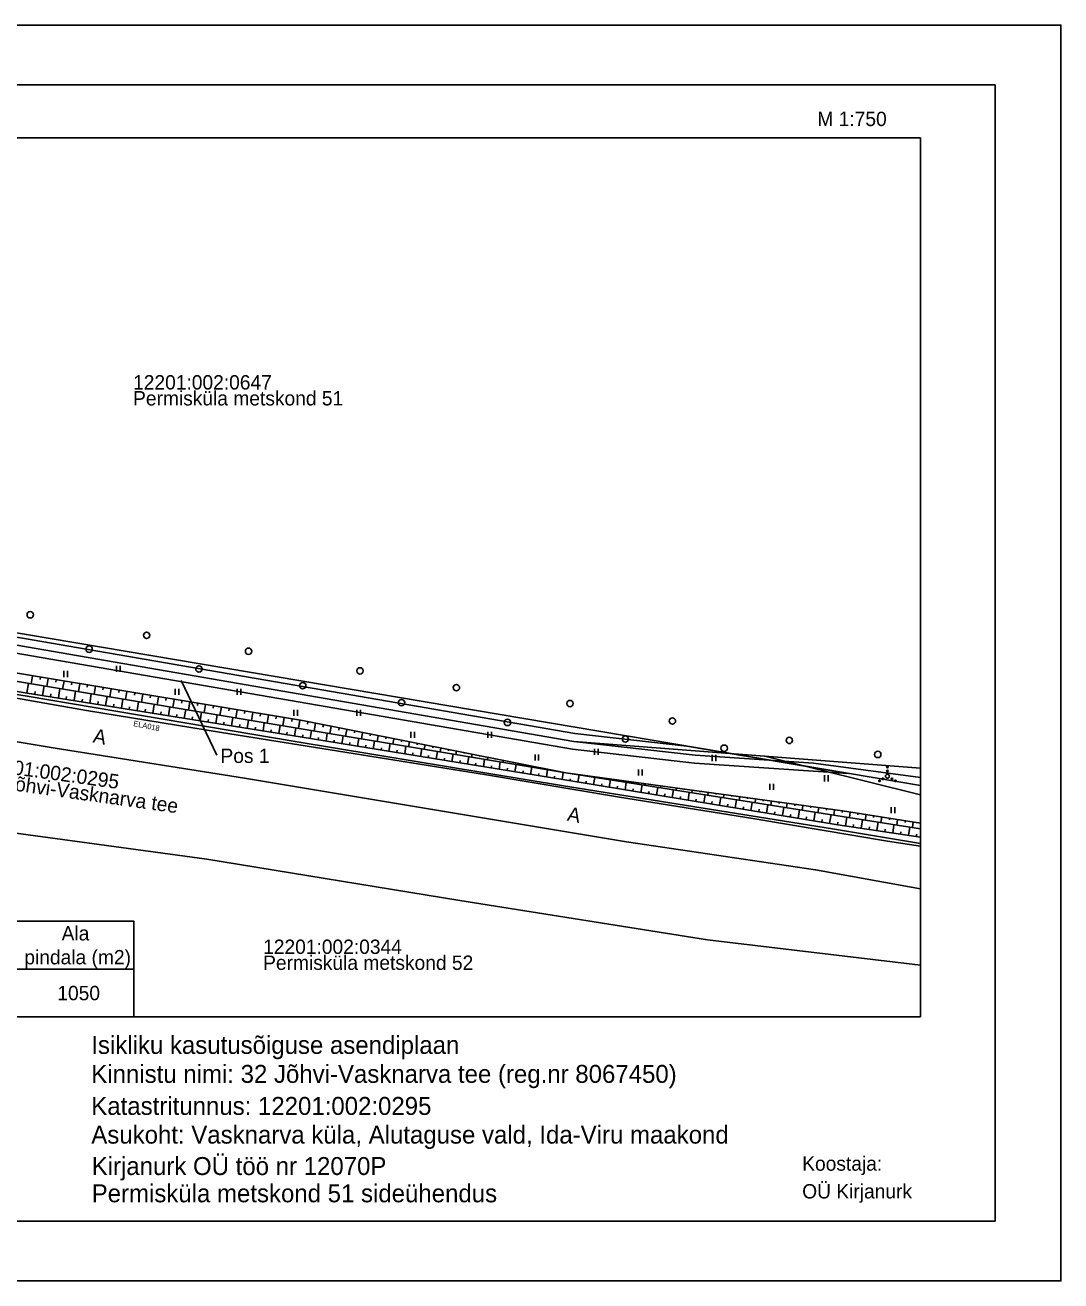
# Model space of a CAD drawing. Extents: x 712851 to 713448, y 6545714 to 6545930.
# Drawn here: x 713318.1 to 713448, y 6545714.1 to 6545871.6 of the extents above; entities that cross this region are included whole.
import ezdxf

# ---------------------------------------------------------------- set-up
doc = ezdxf.new("R2010")
doc.units = 0
for name, color, linetype in [('HALJASTUS', 7, 'Continuous'), ('KASUTUSALA', 7, 'Continuous'), ('PIIR', 7, 'Continuous'), ('PR_SIDE', 7, 'Continuous'), ('RELJEEF', 7, 'Continuous'), ('SITRASS', 7, 'Continuous'), ('TEE', 7, 'Continuous'), ('VORMISTUS_2', 7, 'Continuous')]:
    doc.layers.add(name, color=color, linetype=linetype)

msp = doc.modelspace()

# ---------------------------------------------------------------- linework, layer by layer
at = {"layer": 'HALJASTUS'}
for p, q in [((713322.93, 6545790.63), (713322.93, 6545789.87)), ((713323.39, 6545790.63), (713323.39, 6545789.87)), ((713329.55, 6545791.26), (713329.55, 6545790.5)), ((713330, 6545791.26), (713330, 6545790.5)), ((713336.91, 6545788.38), (713336.91, 6545787.62)), ((713337.36, 6545788.38), (713337.36, 6545787.62)), ((713344.69, 6545788.38), (713344.69, 6545787.62)), ((713345.14, 6545788.38), (713345.14, 6545787.62)), ((713351.78, 6545785.75), (713351.78, 6545784.99)), ((713352.24, 6545785.75), (713352.24, 6545784.99)), ((713359.68, 6545785.75), (713359.68, 6545784.99)), ((713360.14, 6545785.75), (713360.14, 6545784.99)), ((713366.48, 6545782.99), (713366.48, 6545782.23)), ((713366.93, 6545782.99), (713366.93, 6545782.23)), ((713376.11, 6545782.99), (713376.11, 6545782.23)), ((713376.57, 6545782.99), (713376.57, 6545782.23)), ((713389.52, 6545780.87), (713389.52, 6545780.11)), ((713389.98, 6545780.87), (713389.98, 6545780.11)), ((713382.04, 6545780.15), (713382.04, 6545779.39)), ((713382.49, 6545780.15), (713382.49, 6545779.39)), ((713404.24, 6545780.09), (713404.24, 6545779.33)), ((713404.7, 6545780.09), (713404.7, 6545779.33)), ((713395.03, 6545778.26), (713395.03, 6545777.5)), ((713395.48, 6545778.26), (713395.48, 6545777.5)), ((713418.34, 6545777.54), (713418.34, 6545776.78)), ((713418.8, 6545777.54), (713418.8, 6545776.78)), ((713411.49, 6545776.49), (713411.49, 6545775.73)), ((713411.94, 6545776.49), (713411.94, 6545775.73)), ((713426.69, 6545773.56), (713426.69, 6545772.8)), ((713427.15, 6545773.56), (713427.15, 6545772.8))]:
    msp.add_line(p, q, dxfattribs=at)
for points in [[(713430.38, 6545778.43), (713386.9, 6545781.8), (713288.25, 6545798.83), (713243.24, 6545806.02)], [(713430.38, 6545775.09), (713410.87, 6545779.94)]]:
    msp.add_lwpolyline(points, dxfattribs=at)
for centre, radius in [((713318.73, 6545797.68), 0.4), ((713333.33, 6545795.1), 0.4), ((713326.12, 6545793.36), 0.4), ((713346.11, 6545793.1), 0.4), ((713339.89, 6545790.88), 0.4), ((713360.09, 6545790.64), 0.4), ((713352.91, 6545788.78), 0.4), ((713372.18, 6545788.54), 0.4), ((713365.3, 6545786.66), 0.4), ((713386.43, 6545786.54), 0.4), ((713378.59, 6545784.17), 0.4), ((713399.27, 6545784.35), 0.4), ((713393.37, 6545782.1), 0.4), ((713413.93, 6545781.92), 0.4), ((713405.76, 6545780.94), 0.4), ((713425.03, 6545780.16), 0.4), ((713425.67, 6545777.1), 0.1), ((713426.24, 6545777.43), 0.25), ((713426.24, 6545778.58), 0.1), ((713426.24, 6545778.08), 0.1), ((713426.8, 6545777.1), 0.1), ((713425.24, 6545776.85), 0.1), ((713427.24, 6545776.85), 0.1)]:
    msp.add_circle(centre, radius, dxfattribs=at)
at = {"layer": 'KASUTUSALA'}
msp.add_lwpolyline([(713206.31, 6545813.05), (713233.87, 6545808.53), (713288.41, 6545799.81), (713387.04, 6545782.79), (713401.1, 6545781.2), (713421.33, 6545777.78), (713402.03, 6545779.08), (713386.76, 6545780.81), (713288.08, 6545797.84), (713233.55, 6545806.56), (713205.99, 6545811.08)], dxfattribs=at)
at = {"layer": 'PIIR'}
for points in [[(713243.24, 6545807.88), (713424.43, 6545777.26), (713430.38, 6545776.26)], [(713430.38, 6545776.26), (713424.43, 6545777.26), (713243.24, 6545807.88)], [(713243.24, 6545781.2), (713254.77, 6545779.15), (713286.79, 6545774.61), (713312.9, 6545770.82), (713340.87, 6545767.01), (713372.6, 6545761.82), (713403.67, 6545756.92), (713430.38, 6545753.73)], [(713430.38, 6545753.73), (713403.67, 6545756.92), (713372.6, 6545761.82), (713340.87, 6545767.01), (713312.9, 6545770.82), (713286.79, 6545774.61), (713254.77, 6545779.15), (713243.24, 6545781.2)]]:
    msp.add_lwpolyline(points, dxfattribs=at)
at = {"layer": 'PR_SIDE'}
msp.add_lwpolyline([(713243.24, 6545806.02), (713288.25, 6545798.83), (713386.9, 6545781.8), (713402.12, 6545780.08), (713416.97, 6545779.08), (713430.38, 6545777.27)], dxfattribs=at)
at = {"layer": 'RELJEEF'}
for p, q in [((713319.03, 6545790.03), (713318.86, 6545789.02)), ((713320.01, 6545789.86), (713319.96, 6545789.56)), ((713318.31, 6545787.87), (713318.51, 6545789.07)), ((713320.28, 6545787.55), (713320.48, 6545788.75)), ((713321, 6545789.7), (713320.83, 6545788.69)), ((713321.98, 6545789.54), (713321.93, 6545789.23)), ((713322.26, 6545787.24), (713322.45, 6545788.42)), ((713322.97, 6545789.37), (713322.8, 6545788.36)), ((713323.96, 6545789.21), (713323.91, 6545788.9)), ((713324.94, 6545789.04), (713324.78, 6545788.03)), ((713325.93, 6545788.88), (713325.88, 6545788.58)), ((713326.92, 6545788.72), (713326.75, 6545787.7)), ((713327.9, 6545788.55), (713327.85, 6545788.25)), ((713328.89, 6545788.39), (713328.72, 6545787.37)), ((713329.88, 6545788.22), (713329.83, 6545787.92)), ((713319.3, 6545787.71), (713319.35, 6545788.07)), ((713321.27, 6545787.39), (713321.33, 6545787.75)), ((713323.25, 6545787.08), (713323.3, 6545787.43)), ((713324.23, 6545786.92), (713324.42, 6545788.09)), ((713325.22, 6545786.76), (713325.28, 6545787.11)), ((713326.21, 6545786.6), (713326.39, 6545787.76)), ((713327.19, 6545786.44), (713327.25, 6545786.79)), ((713328.18, 6545786.28), (713328.37, 6545787.43)), ((713330.16, 6545785.97), (713330.34, 6545787.1)), ((713330.86, 6545788.06), (713330.69, 6545787.04)), ((713331.85, 6545787.89), (713331.8, 6545787.59)), ((713332.13, 6545785.65), (713332.31, 6545786.77)), ((713332.84, 6545787.73), (713332.67, 6545786.71)), ((713333.82, 6545787.57), (713333.77, 6545787.26)), ((713334.81, 6545787.4), (713334.64, 6545786.39)), ((713335.79, 6545787.24), (713335.74, 6545786.93)), ((713336.78, 6545787.07), (713336.61, 6545786.06)), ((713337.77, 6545786.91), (713337.72, 6545786.6)), ((713338.75, 6545786.75), (713338.58, 6545785.73)), ((713329.17, 6545786.12), (713329.22, 6545786.47)), ((713331.14, 6545785.81), (713331.2, 6545786.15)), ((713333.12, 6545785.49), (713333.17, 6545785.83)), ((713334.11, 6545785.33), (713334.28, 6545786.44)), ((713335.09, 6545785.17), (713335.15, 6545785.5)), ((713336.08, 6545785.01), (713336.26, 6545786.12)), ((713337.07, 6545784.85), (713337.12, 6545785.18)), ((713338.05, 6545784.7), (713338.23, 6545785.79)), ((713339.74, 6545786.58), (713339.69, 6545786.28)), ((713340.03, 6545784.38), (713340.2, 6545785.46)), ((713340.73, 6545786.42), (713340.56, 6545785.4)), ((713341.71, 6545786.25), (713341.66, 6545785.95)), ((713342, 6545784.06), (713342.18, 6545785.13)), ((713342.7, 6545786.09), (713342.53, 6545785.07)), ((713343.69, 6545785.92), (713343.64, 6545785.62)), ((713344.67, 6545785.76), (713344.5, 6545784.74)), ((713345.66, 6545785.6), (713345.61, 6545785.29)), ((713346.65, 6545785.43), (713346.48, 6545784.41)), ((713347.63, 6545785.27), (713347.58, 6545784.96)), ((713348.62, 6545785.1), (713348.45, 6545784.08)), ((713339.04, 6545784.54), (713339.09, 6545784.86)), ((713341.02, 6545784.22), (713341.07, 6545784.54)), ((713342.99, 6545783.9), (713343.04, 6545784.22)), ((713343.98, 6545783.74), (713344.15, 6545784.8)), ((713344.97, 6545783.58), (713345.02, 6545783.9)), ((713345.95, 6545783.43), (713346.12, 6545784.47)), ((713346.94, 6545783.27), (713346.99, 6545783.58)), ((713347.93, 6545783.11), (713348.09, 6545784.14)), ((713349.6, 6545784.94), (713349.55, 6545784.63)), ((713349.9, 6545782.79), (713350.07, 6545783.81)), ((713350.59, 6545784.78), (713350.42, 6545783.76)), ((713351.58, 6545784.61), (713351.53, 6545784.3)), ((713351.88, 6545782.47), (713352.04, 6545783.49)), ((713352.56, 6545784.45), (713352.39, 6545783.43)), ((713353.55, 6545784.26), (713353.49, 6545783.96)), ((713354.53, 6545784.07), (713354.34, 6545783.1)), ((713355.51, 6545783.87), (713355.45, 6545783.59)), ((713356.49, 6545783.68), (713356.31, 6545782.78)), ((713357.47, 6545783.48), (713357.42, 6545783.22)), ((713348.92, 6545782.95), (713348.97, 6545783.26)), ((713350.89, 6545782.63), (713350.94, 6545782.94)), ((713352.86, 6545782.31), (713352.91, 6545782.62)), ((713353.85, 6545782.15), (713354.01, 6545783.16)), ((713354.84, 6545781.99), (713354.89, 6545782.29)), ((713355.83, 6545781.83), (713355.99, 6545782.83)), ((713356.81, 6545781.67), (713356.86, 6545781.97)), ((713357.8, 6545781.51), (713357.96, 6545782.5)), ((713358.45, 6545783.29), (713358.28, 6545782.45)), ((713359.43, 6545783.1), (713359.38, 6545782.85)), ((713359.77, 6545781.19), (713359.93, 6545782.17)), ((713360.41, 6545782.9), (713360.26, 6545782.12)), ((713361.39, 6545782.71), (713361.35, 6545782.48)), ((713362.38, 6545782.51), (713362.23, 6545781.79)), ((713363.36, 6545782.32), (713363.32, 6545782.11)), ((713364.34, 6545782.12), (713364.21, 6545781.46)), ((713365.32, 6545781.93), (713365.28, 6545781.74)), ((713358.79, 6545781.35), (713358.83, 6545781.65)), ((713360.76, 6545781.03), (713360.81, 6545781.32)), ((713361.75, 6545780.87), (713361.91, 6545781.84)), ((713362.73, 6545780.71), (713362.78, 6545781)), ((713363.72, 6545780.55), (713363.88, 6545781.52)), ((713364.71, 6545780.39), (713364.76, 6545780.68)), ((713365.7, 6545780.23), (713365.85, 6545781.19)), ((713366.3, 6545781.74), (713366.18, 6545781.13)), ((713366.68, 6545780.07), (713366.73, 6545780.35)), ((713367.28, 6545781.54), (713367.25, 6545781.37)), ((713367.67, 6545779.91), (713367.83, 6545780.86)), ((713368.26, 6545781.35), (713368.15, 6545780.81)), ((713369.24, 6545781.15), (713369.21, 6545781)), ((713369.64, 6545779.59), (713369.8, 6545780.53)), ((713370.22, 6545780.96), (713370.13, 6545780.48)), ((713371.2, 6545780.76), (713371.18, 6545780.63)), ((713372.18, 6545780.57), (713372.1, 6545780.15)), ((713373.17, 6545780.38), (713373.14, 6545780.26)), ((713368.66, 6545779.75), (713368.7, 6545780.03)), ((713370.63, 6545779.43), (713370.68, 6545779.71)), ((713371.62, 6545779.26), (713371.77, 6545780.2)), ((713372.61, 6545779.1), (713372.65, 6545779.38)), ((713373.59, 6545778.94), (713373.74, 6545779.88)), ((713374.15, 6545780.18), (713374.07, 6545779.82)), ((713374.58, 6545778.78), (713374.62, 6545779.06)), ((713375.13, 6545779.99), (713375.11, 6545779.89)), ((713375.57, 6545778.62), (713375.72, 6545779.55)), ((713376.11, 6545779.79), (713376.05, 6545779.49)), ((713377.09, 6545779.6), (713377.07, 6545779.52)), ((713377.54, 6545778.3), (713377.69, 6545779.22)), ((713378.07, 6545779.4), (713378.02, 6545779.16)), ((713379.05, 6545779.21), (713379.04, 6545779.15)), ((713379.51, 6545777.98), (713379.66, 6545778.89)), ((713380.03, 6545779.02), (713380, 6545778.84)), ((713381.01, 6545778.82), (713381, 6545778.78)), ((713376.55, 6545778.46), (713376.6, 6545778.74)), ((713378.53, 6545778.14), (713378.57, 6545778.42)), ((713380.5, 6545777.82), (713380.55, 6545778.09)), ((713381.49, 6545777.66), (713381.64, 6545778.56)), ((713381.99, 6545778.63), (713381.97, 6545778.51)), ((713382.48, 6545777.5), (713382.52, 6545777.77)), ((713382.98, 6545778.43), (713382.97, 6545778.41)), ((713383.46, 6545777.34), (713383.61, 6545778.23)), ((713383.96, 6545778.24), (713383.94, 6545778.18)), ((713384.45, 6545777.18), (713384.49, 6545777.45)), ((713384.94, 6545778.04), (713384.94, 6545778.04)), ((713385.44, 6545777.02), (713385.58, 6545777.91)), ((713385.92, 6545777.85), (713385.92, 6545777.85)), ((713386.91, 6545777.71), (713386.91, 6545777.71)), ((713387.41, 6545776.7), (713387.56, 6545777.59)), ((713387.9, 6545777.58), (713387.89, 6545777.54)), ((713388.89, 6545777.44), (713388.89, 6545777.42)), ((713389.38, 6545776.37), (713389.53, 6545777.28)), ((713389.88, 6545777.31), (713389.87, 6545777.23)), ((713386.42, 6545776.86), (713386.47, 6545777.12)), ((713388.4, 6545776.53), (713388.44, 6545776.8)), ((713390.37, 6545776.21), (713390.42, 6545776.48)), ((713390.87, 6545777.17), (713390.87, 6545777.14)), ((713391.36, 6545776.05), (713391.51, 6545776.97)), ((713391.86, 6545777.04), (713391.85, 6545776.91)), ((713392.34, 6545775.89), (713392.39, 6545776.16)), ((713392.85, 6545776.9), (713392.85, 6545776.86)), ((713393.33, 6545775.72), (713393.48, 6545776.65)), ((713393.84, 6545776.76), (713393.82, 6545776.6)), ((713394.32, 6545775.56), (713394.36, 6545775.84)), ((713394.83, 6545776.63), (713394.83, 6545776.57)), ((713395.31, 6545775.4), (713395.46, 6545776.34)), ((713395.83, 6545776.49), (713395.8, 6545776.29)), ((713396.82, 6545776.36), (713396.81, 6545776.29)), ((713397.28, 6545775.08), (713397.43, 6545776.03)), ((713397.81, 6545776.22), (713397.77, 6545775.98)), ((713398.8, 6545776.08), (713398.79, 6545776)), ((713399.25, 6545774.75), (713399.41, 6545775.72)), ((713399.79, 6545775.95), (713399.75, 6545775.66)), ((713400.78, 6545775.81), (713400.77, 6545775.72)), ((713401.77, 6545775.68), (713401.72, 6545775.35)), ((713396.29, 6545775.24), (713396.34, 6545775.52)), ((713398.27, 6545774.91), (713398.31, 6545775.2)), ((713400.24, 6545774.59), (713400.29, 6545774.88)), ((713401.23, 6545774.43), (713401.39, 6545775.4)), ((713402.21, 6545774.27), (713402.26, 6545774.56)), ((713402.76, 6545775.54), (713402.75, 6545775.44)), ((713403.2, 6545774.11), (713403.36, 6545775.09)), ((713403.75, 6545775.41), (713403.7, 6545775.04)), ((713404.19, 6545773.94), (713404.24, 6545774.24)), ((713404.74, 6545775.27), (713404.73, 6545775.15)), ((713405.17, 6545773.78), (713405.34, 6545774.78)), ((713405.73, 6545775.13), (713405.68, 6545774.72)), ((713406.72, 6545775), (713406.71, 6545774.87)), ((713407.15, 6545773.46), (713407.31, 6545774.47)), ((713407.71, 6545774.86), (713407.65, 6545774.41)), ((713408.7, 6545774.73), (713408.69, 6545774.58)), ((713409.12, 6545773.13), (713409.29, 6545774.15)), ((713409.7, 6545774.59), (713409.63, 6545774.1)), ((713410.69, 6545774.45), (713410.67, 6545774.3)), ((713411.68, 6545774.32), (713411.6, 6545773.79)), ((713412.67, 6545774.18), (713412.64, 6545774.02)), ((713413.66, 6545774.05), (713413.58, 6545773.47)), ((713406.16, 6545773.62), (713406.21, 6545773.92)), ((713408.13, 6545773.3), (713408.18, 6545773.6)), ((713410.11, 6545772.97), (713410.16, 6545773.28)), ((713411.09, 6545772.81), (713411.26, 6545773.84)), ((713412.08, 6545772.65), (713412.13, 6545772.96)), ((713413.07, 6545772.49), (713413.24, 6545773.53)), ((713414.05, 6545772.32), (713414.11, 6545772.64)), ((713414.65, 6545773.91), (713414.62, 6545773.73)), ((713415.04, 6545772.16), (713415.21, 6545773.22)), ((713415.64, 6545773.77), (713415.56, 6545773.16)), ((713416.63, 6545773.64), (713416.6, 6545773.45)), ((713417.02, 6545771.84), (713417.19, 6545772.9)), ((713417.62, 6545773.5), (713417.53, 6545772.85)), ((713418.61, 6545773.37), (713418.58, 6545773.17)), ((713418.99, 6545771.52), (713419.17, 6545772.59)), ((713419.6, 6545773.23), (713419.51, 6545772.54)), ((713420.59, 6545773.1), (713420.56, 6545772.88)), ((713421.58, 6545772.94), (713421.47, 6545772.23)), ((713422.57, 6545772.78), (713422.54, 6545772.57)), ((713423.56, 6545772.63), (713423.44, 6545771.92)), ((713424.54, 6545772.47), (713424.51, 6545772.26)), ((713416.03, 6545772), (713416.08, 6545772.32)), ((713418, 6545771.68), (713418.05, 6545772)), ((713419.98, 6545771.35), (713420.03, 6545771.68)), ((713420.96, 6545771.2), (713421.13, 6545772.28)), ((713421.95, 6545771.05), (713422, 6545771.38)), ((713422.94, 6545770.9), (713423.1, 6545771.97)), ((713423.93, 6545770.75), (713423.98, 6545771.07)), ((713424.92, 6545770.6), (713425.08, 6545771.66)), ((713425.53, 6545772.32), (713425.42, 6545771.61)), ((713426.52, 6545772.16), (713426.49, 6545771.95)), ((713426.9, 6545770.3), (713427.06, 6545771.35)), ((713427.51, 6545772), (713427.4, 6545771.3)), ((713428.5, 6545771.85), (713428.46, 6545771.64)), ((713428.87, 6545770), (713429.03, 6545771.04)), ((713429.48, 6545771.69), (713429.37, 6545770.99)), ((713425.91, 6545770.45), (713425.96, 6545770.77)), ((713427.88, 6545770.15), (713427.93, 6545770.47)), ((713429.86, 6545769.85), (713429.91, 6545770.16))]:
    msp.add_line(p, q, dxfattribs=at)
for points in [[(713430.38, 6545771.55), (713420.62, 6545773.09), (713385.92, 6545777.85), (713352.88, 6545784.4), (713285.38, 6545795.63), (713263.03, 6545798.62), (713243.24, 6545801.93)], [(713430.38, 6545770.83), (713420.58, 6545772.37), (713385.92, 6545777.85), (713352.73, 6545783.37), (713318.62, 6545789.06), (713285.17, 6545794.57), (713263.06, 6545797.93), (713243.24, 6545801.22)], [(713430.38, 6545769.77), (713420.01, 6545771.35), (713385.79, 6545776.96), (713352.57, 6545782.36), (713318.35, 6545787.86), (713284.88, 6545793.54), (713262.93, 6545796.77), (713243.24, 6545800.24)]]:
    msp.add_lwpolyline(points, dxfattribs=at)
at = {"layer": 'SITRASS'}
msp.add_lwpolyline([(713243.24, 6545799.36), (713258.87, 6545796.57), (713275.26, 6545794.2), (713291.96, 6545791.3), (713308.65, 6545788.66), (713325.8, 6545785.69), (713342.72, 6545782.93), (713359.23, 6545780.27), (713375.97, 6545777.6), (713392.4, 6545774.84), (713409.59, 6545772.08), (713426.26, 6545769.29), (713430.38, 6545768.65)], dxfattribs=at)
at = {"layer": 'TEE'}
for points in [[(713430.38, 6545769.01), (713419.37, 6545770.81), (713385.61, 6545776.24), (713352.22, 6545781.76), (713318.36, 6545787.48), (713284.78, 6545792.77), (713262.98, 6545796.29), (713243.24, 6545799.61)], [(713243.24, 6545793.65), (713247.87, 6545792.88), (713272.59, 6545788.96), (713297.06, 6545785.08), (713321.86, 6545780.95), (713345.59, 6545777.19), (713369.19, 6545773.26), (713393.52, 6545769.18), (713417.23, 6545765.7), (713430.38, 6545763.32)]]:
    msp.add_lwpolyline(points, dxfattribs=at)
at = {"layer": 'VORMISTUS_2'}
for p, q in [((713337.65, 6545789.43), (713342.12, 6545780.07)), ((713243.24, 6545753.23), (713331.74, 6545753.23)), ((713439.74, 6545721.63), (713439.74, 6545721.63))]:
    msp.add_line(p, q, dxfattribs=at)
for points in [[(713225.24, 6545871.63), (713447.99, 6545871.63), (713447.99, 6545714.13), (713225.24, 6545714.13)], [(713233.49, 6545721.63), (713233.49, 6545864.13), (713439.74, 6545864.13), (713439.74, 6545721.63)], [(713233.49, 6545864.13), (713439.74, 6545864.13), (713439.74, 6545721.63), (713233.49, 6545721.63)], [(713430.38, 6545747.23), (713430.38, 6545857.48), (713243.24, 6545857.48), (713243.24, 6545747.23)], [(713243.24, 6545759.23), (713331.74, 6545759.23), (713331.74, 6545747.23), (713243.24, 6545747.23)]]:
    msp.add_lwpolyline(points, close=True, dxfattribs=at)
for points in [[(713430.38, 6545857.48), (713243.24, 6545857.48)], [(713430.38, 6545747.23), (713430.38, 6545857.48)], [(713243.24, 6545747.23), (713430.38, 6545747.23)]]:
    msp.add_lwpolyline(points, dxfattribs=at)

# ---------------------------------------------------------------- texts
at = {"layer": 'PIIR'}
for s, p in [('12201:002:0647', (713331.63, 6545825.93)), ('Permisküla metskond 51', (713331.63, 6545823.93)), ('12201:002:0344', (713347.94, 6545755.14)), ('Permisküla metskond 52', (713347.94, 6545753.14))]:
    msp.add_text(s, height=1.8, dxfattribs=at).set_placement(p)
for s, p in [('12201:002:0295', (713312.51, 6545778.23)), ('32 Jõhvi-Vasknarva tee', (713312.24, 6545776.25))]:
    msp.add_text(s, height=1.8, rotation=352.0606, dxfattribs=at).set_placement(p)
at = {"layer": 'SITRASS'}
msp.add_text('ELA018', height=0.7, rotation=348.5395, dxfattribs=at).set_placement((713331.62, 6545783.73))
at = {"layer": 'TEE'}
for p in [(713326.51, 6545781.68), (713385.99, 6545771.87)]:
    msp.add_text('A', height=1.8, rotation=348.682, dxfattribs=at).set_placement(p)
at = {"layer": 'VORMISTUS_2'}
for s, height, p in [('M 1:750', 1.8, (713417.45, 6545858.97)), ('Kirjanurk OÜ töö nr 12070P', 2.25, (713326.44, 6545727.41)), ('Permisküla metskond 51 sideühendus', 2.25, (713326.44, 6545723.99))]:
    msp.add_text(s, height=height, rotation=360, dxfattribs=at).set_placement(p)
for s, height, p in [('Pos 1', 1.8, (713342.59, 6545779.09)), ('Ala', 1.8, (713322.67, 6545756.83)), ('pindala (m2)', 1.8, (713317.99, 6545753.83)), ('1050', 1.8, (713322.13, 6545749.33)), ('Isikliku kasutusõiguse asendiplaan', 2.25, (713326.39, 6545742.6)), ('Kinnistu nimi: 32 Jõhvi-Vasknarva tee (reg.nr 8067450)', 2.25, (713326.39, 6545738.97)), ('Katastritunnus: 12201:002:0295', 2.25, (713326.39, 6545734.95)), ('Asukoht: Vasknarva küla, Alutaguse vald, Ida-Viru maakond', 2.25, (713326.39, 6545731.35)), ('Koostaja:', 1.8, (713415.55, 6545727.95)), ('OÜ Kirjanurk', 1.8, (713415.55, 6545724.47))]:
    msp.add_text(s, height=height, dxfattribs=at).set_placement(p)

doc.saveas('drawing.dxf')
